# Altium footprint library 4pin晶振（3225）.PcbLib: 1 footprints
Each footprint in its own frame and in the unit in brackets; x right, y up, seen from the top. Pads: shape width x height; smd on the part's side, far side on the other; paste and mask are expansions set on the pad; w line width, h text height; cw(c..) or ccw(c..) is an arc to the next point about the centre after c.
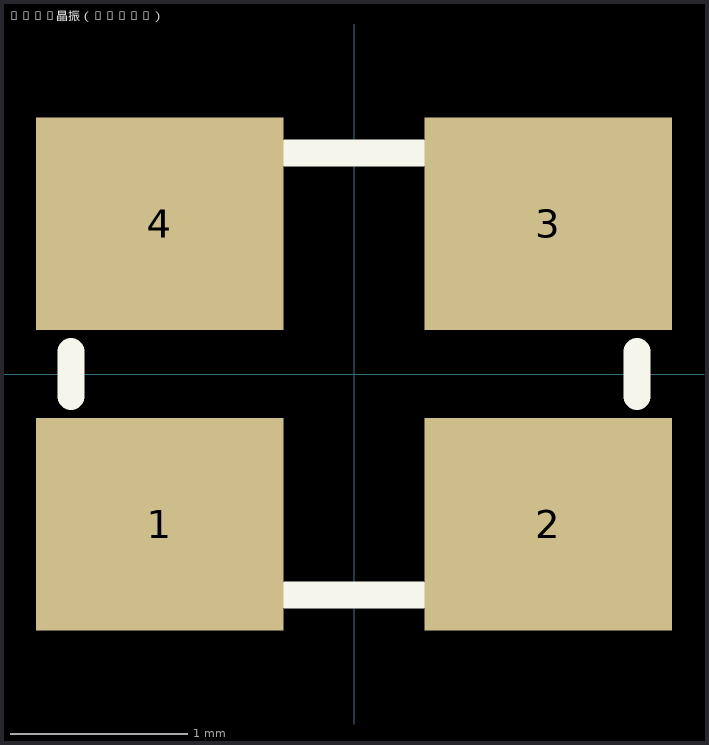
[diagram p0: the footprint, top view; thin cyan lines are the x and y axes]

## 4pin晶振（FA238） [mm] "4pin晶振（FA238）"
pads (4):
  rect 1.4x1.2 smd: 1(-1.1,-0.85) 2(1.1,-0.85) 3(1.1,0.85) 4(-1.1,0.85)
Top Overlay:
  lines w0.152: -1.6,-0.127 -1.6,0.127 ; -0.381,-1.25 0.381,-1.25 ; -0.381,1.25 0.381,1.25 ; 1.6,-0.127 1.6,0.127
  text "." at -2.159,-1.27 h0.91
